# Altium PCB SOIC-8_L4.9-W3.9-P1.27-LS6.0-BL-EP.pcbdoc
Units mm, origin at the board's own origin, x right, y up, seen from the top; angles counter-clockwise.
Board outline 18.03 x 20.08 mm, 2 copper layers (Top Layer, Bottom Layer), stack 0 mm thick; 1 components, 0 nets, 9 pads, 4 vias.
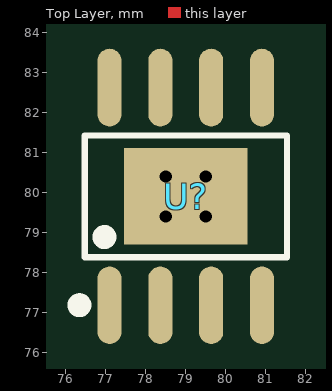
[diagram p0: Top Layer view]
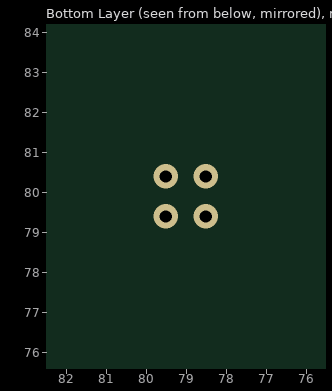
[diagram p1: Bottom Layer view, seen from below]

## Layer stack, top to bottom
Top Layer: signal copper (thickness not stored)
Bottom Layer: signal copper (thickness not stored)

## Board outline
87.885,69.85 69.85,69.85 69.85,89.932 87.885,89.932

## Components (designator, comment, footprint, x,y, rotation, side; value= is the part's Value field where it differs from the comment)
U? "" SOIC-8_L4.9-W3.9-P1.27-LS6.0-BL-EP 79.008,79.891 r0 top

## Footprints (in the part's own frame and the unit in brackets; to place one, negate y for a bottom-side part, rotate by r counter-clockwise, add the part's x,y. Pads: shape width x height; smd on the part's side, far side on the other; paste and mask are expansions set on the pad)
SOIC-8_L4.9-W3.9-P1.27-LS6.0-BL-EP [mm]
  oval 0.602x1.941 smd: 1(-1.905,-2.721) 2(-0.635,-2.721) 3(0.635,-2.721) 4(1.905,-2.721) 5(1.905,2.721) 6(0.635,2.721) 7(-0.635,2.721) 8(-1.905,2.721)
  rect 3.098x2.41 smd: 9(0,0)
  silkscreen extent -2.81,-2.87 2.53,1.52

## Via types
v1: diameter 0.61, hole 0.305, Top Layer to Bottom Layer, 4 vias

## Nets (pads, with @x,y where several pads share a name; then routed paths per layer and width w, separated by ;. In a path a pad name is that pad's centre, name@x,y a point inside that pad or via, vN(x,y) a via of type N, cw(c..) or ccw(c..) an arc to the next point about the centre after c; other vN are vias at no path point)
pads on no net: U?.1 U?.2 U?.3 U?.4 U?.5 U?.6 U?.7 U?.8 U?.9
copper on no net:
  other v1: 78.509,79.391 79.509,79.391 78.509,80.391 79.509,80.391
